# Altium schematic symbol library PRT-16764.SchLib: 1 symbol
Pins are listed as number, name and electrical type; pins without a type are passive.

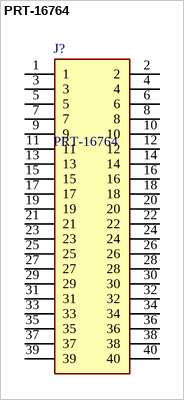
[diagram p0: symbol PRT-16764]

## PRT-16764
designator J?
Headers & Wire Housings Extended GPIO Female Header - 2x20 Pin (13.5mm/9.80mm); Manufacturer_Name: SparkFun; Geometry.Height: 13.75mm
footprint RHDR40W64P254_2X20_5130X500X1375P
pins: 1, 2, 3, 4, 5, 6, 7, 8, 9, 10, 11, 12, 13, 14, 15, 16, 17, 18, 19, 20, 21, 22, 23, 24, 25, 26, 27, 28, 29, 30, 31, 32, 33, 34, 35, 36, 37, 38, 39, 40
